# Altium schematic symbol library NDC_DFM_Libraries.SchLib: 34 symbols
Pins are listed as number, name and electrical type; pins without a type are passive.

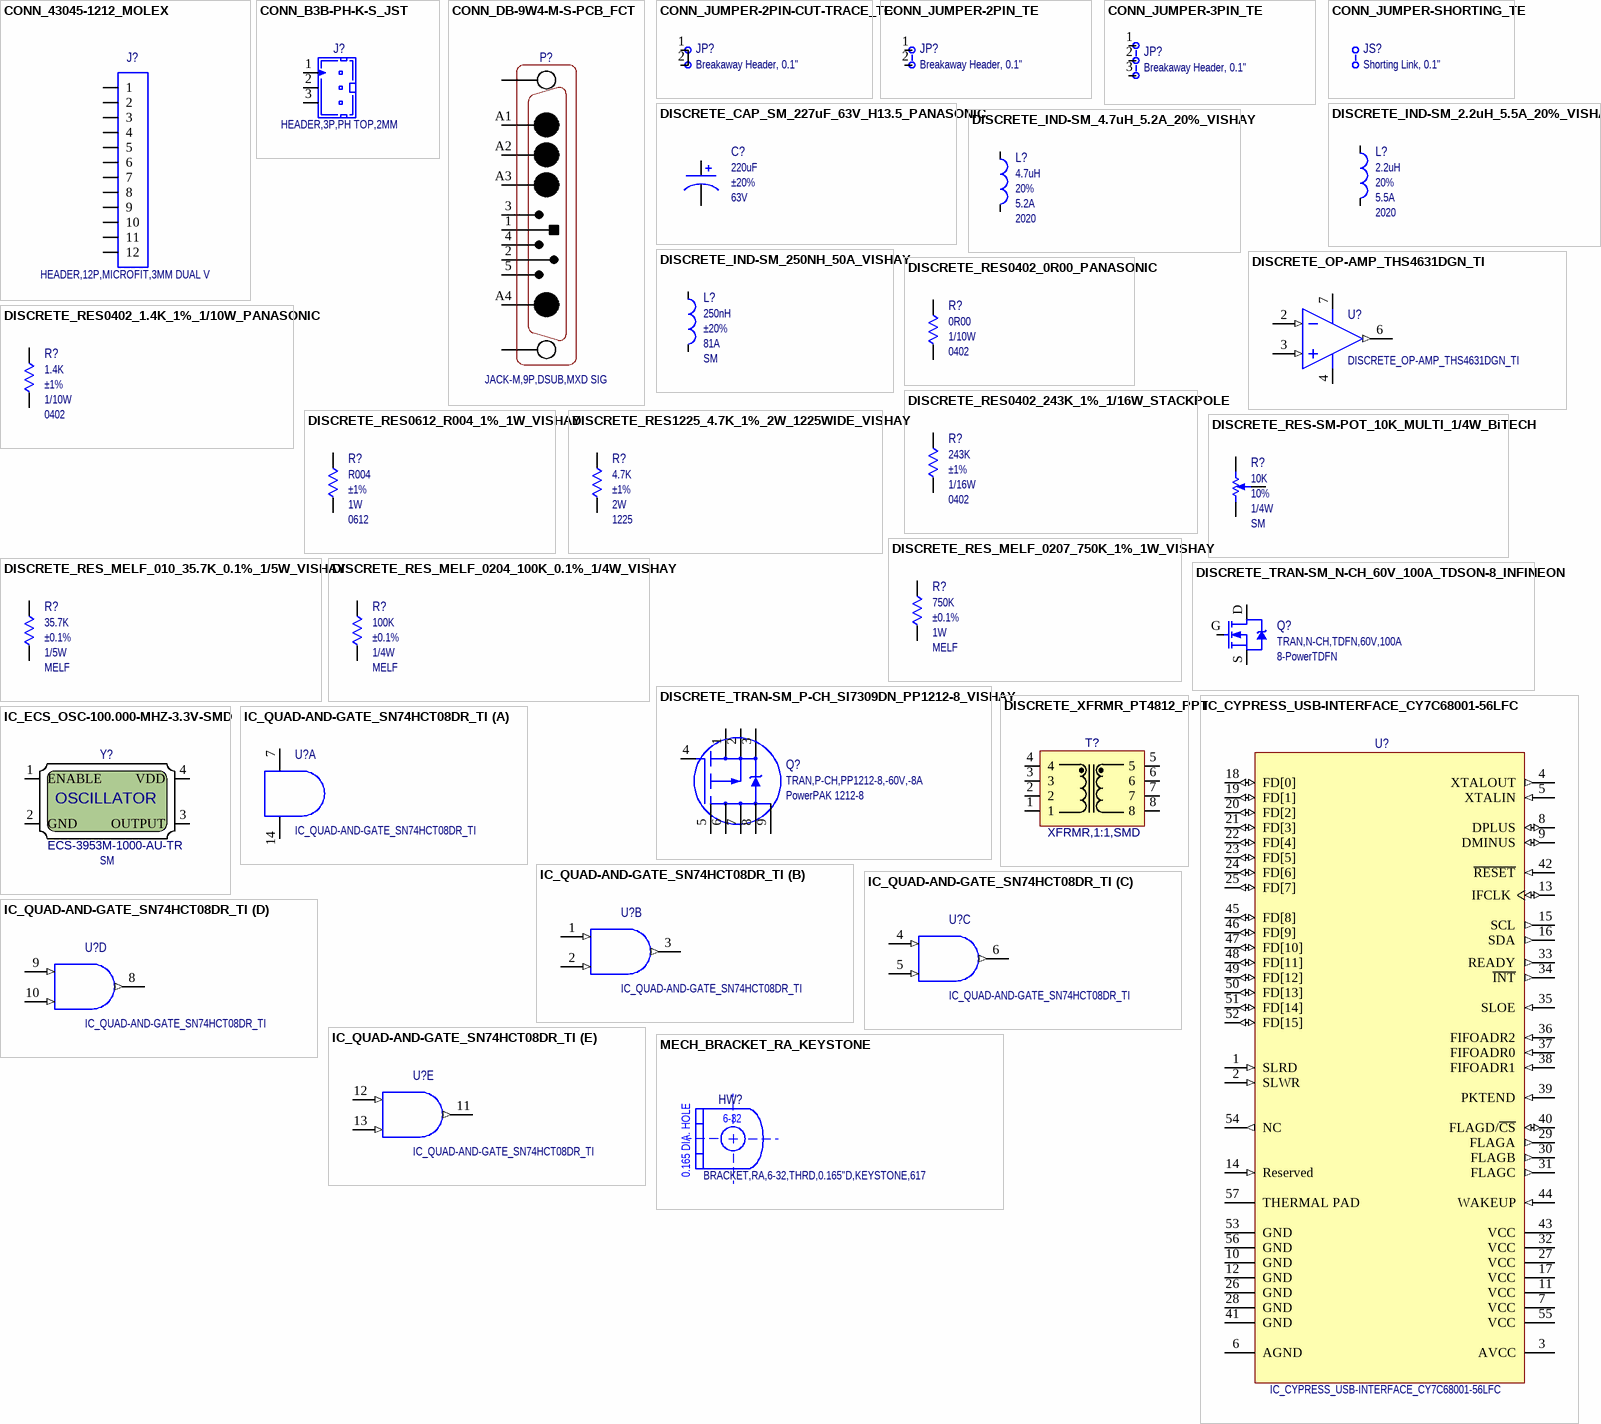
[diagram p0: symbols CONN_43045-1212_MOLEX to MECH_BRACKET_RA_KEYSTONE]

## CONN_43045-1212_MOLEX
designator J?, comment HEADER,12P,MICROFIT,3MM DUAL V
Manufacturer Part Number: 43045-1212; Manufacturer: MOLEX; CompanyPN: 1004237
footprint Molex_43045-1212 (Header, 12 Position, Pitch 3.0mm, Body 21.65 mm L X 7.37mm W, Height 9.91mm)
pins: 1, 2, 3, 4, 5, 6, 7, 8, 9, 10, 11, 12

## CONN_B3B-PH-K-S_JST
designator J?, comment HEADER,3P,PH TOP,2MM
Manufacturer: JST Sales America Inc; Manufacturer Part Number: B3B-PH-K-S(LF)(SN); CompanyPN: 1004223; Value: 2.00mm
footprint JST_B3B-PH-K-S
pins: 1 (power), 2 (power), 3 (power)

## CONN_DB-9W4-M-S-PCB_FCT
designator P?, comment JACK-M,9P,DSUB,MXD SIG
Manufacturer: FCT ELECTRONICS; Manufacturer Part Number: FM9W4P1-2519; CompanyPN: 1004225
footprint FCT_DB-9W4-M-S-PCB-MOD (FCT FM9W4P1-2464, Conn, DB, Mixed, 9 Pins, 4 Wide, Male, Straight, PCB Mt)
pins: 1, 2, 3, 4, 5, A1 (power), A2 (power), A3 (power), A4, C, C

## CONN_JUMPER-2PIN-CUT-TRACE_TE
designator JP?, comment Breakaway Header, 0.1"
Breakaway Header, 2.54mm (0.1") Pitch; Manufacturer: TE Connectivity / AMP; Manufacturer Part Number: 826646-2; CompanyPN: 1004233
footprint TE_HDR1X2-CUT-TRACE (Connector; Header; 2 Position)
pins: 1, 2

## CONN_JUMPER-2PIN_TE
designator JP?, comment Breakaway Header, 0.1"
Breakaway Header, 2.54mm (0.1") Pitch; Manufacturer: TE Connectivity / AMP; Manufacturer Part Number: 826646-2; CompanyPN: 1004232
footprint TE_HDR1X2 (Connector; Header; 2 Position)
pins: 1, 2

## CONN_JUMPER-3PIN_TE
designator JP?, comment Breakaway Header, 0.1"
Breakaway Header, 2.54mm (0.1") Pitch; Manufacturer: TE Connectivity / AMP; Manufacturer Part Number: 826646-2; CompanyPN: 1004234
footprint TE_HDR1X3 (Connector; Header; 3 Position)
pins: 1, 2, 3

## CONN_JUMPER-SHORTING_TE
designator JS?, comment Shorting Link, 0.1"  (mechanical)
Shorting Link, 2.54mm (0.1") Pitch; Manufacturer: Sullins Connector Solutions; Manufacturer Part Number: NPN02SXLN-RC; CompanyPN: 1004235
footprint SULLINS_JMPR-SOCKET-1X2

## DISCRETE_CAP_SM_227uF_63V_H13.5_PANASONIC
designator C?, comment value 220uF  Tolerance: ±20%  Voltage Rating: 63V  (hidden comment: CAP,ALUM,227,63V,20%,SMD)
Manufacturer: Panasonic Electronic Components; Manufacturer Part Number: EEV-FK1J221Q; CompanyPN: 1004222
footprint Panasonic_CAP_SM_H13
pins: 1, 2

## DISCRETE_IND-SM_2.2uH_5.5A_20%_VISHAY
designator L?, comment value 2.2uH  Package / Case: 2020  Tolerance: 20%  SatCur: 5.5A  (hidden comment: IND,2.2uH,2020,5.5A,20%)
Manufacturer: Vishay / Dale; Manufacturer Part Number: IHLP2020CZER2R2M11; CompanyPN: 1004229
footprint VISHAY_IND-IHLP2020CZ-11 (Low Profile, High Current IHLP® Inductor)
pins: 1, 2

## DISCRETE_IND-SM_4.7uH_5.2A_20%_VISHAY
designator L?, comment value 4.7uH  Package / Case: 2020  Tolerance: 20%  SatCur: 5.2A  (hidden comment: IND,4.7uH,202,5.2A,20%)
Manufacturer: Vishay / Dale; Manufacturer Part Number: IHLP2020CZER4R7M11; CompanyPN: 1004230
footprint VISHAY_IND-IHLP2020CZ-11 (Low Profile, High Current IHLP® Inductor)
pins: 1, 2

## DISCRETE_IND-SM_250NH_50A_VISHAY
designator L?, comment value 250nH  Tolerance: ±20%  PKG: SM  SatCur: 81A  (hidden comment: IND,250nH,SM,50A,81A ISAT)
Manufacturer: Wurth Electronics Inc; Manufacturer Part Number: 744309025; CompanyPN: 1004231
footprint VISHAY-IND-WE-HCM (WE-HCM SMD High-Current Flat Wire Inductor)
pins: 1, 2

## DISCRETE_OP-AMP_THS4631DGN_TI
designator U?
Operational Amplifier; Manufacturer: Texas Instruments; CompanyPN: 1004247
footprint TI_DGN8-EP (TSOP, 8-Leads, Body 3.1x3.1mm (max), Pitch 0.65mm, IPC Medium Density)
pins: 1 NC hidden, 2 IN- (in), 3 IN+ (in), 4 V- (power), 6 OUT (out), 7 V+ (power), 8 NC hidden

## DISCRETE_RES0402_0R00_PANASONIC
designator R?, comment value 0R00  Power: 1/10W  PKG: 0402  (hidden comment: RES,0R00,0402,1/10W)
Manufacturer Part Number: ERJ-2GE0R00X; Manufacturer: PANASONIC ELECTRONIC COMPONENTS; CompanyPN: 1004243; Voltage Rating: 50V
footprint STACKPOLE_RESC1005X04N(0402) (Chip Resistor, Body 1.0x0.5mm, Height 0.40mm, IPC Medium Density)
pins: 1, 2

## DISCRETE_RES0402_1.4K_1%_1/10W_PANASONIC
designator R?, comment value 1.4K  TOLERANCE: ±1%  Power: 1/10W  PKG: 0402  (hidden comment: RES,1.4K,0402,1%,1/10W)
Manufacturer Part Number: ERJ2RKF1401X; Manufacturer: PANASONIC ELECTRONIC COMPONENTS; CompanyPN: 1004244; Voltage Rating: 50V
footprint STACKPOLE_RESC1005X04N(0402) (Chip Resistor, Body 1.0x0.5mm, Height 0.40mm, IPC Medium Density)
pins: 1, 2

## DISCRETE_RES0402_243K_1%_1/16W_STACKPOLE
designator R?, comment value 243K  Tolerance: ±1%  Power: 1/16W  PKG: 0402  (hidden comment: RES,243K,0402,1%,1/16W)
Manufacturer: Stackpole Electronics Inc; Manufacturer Part Number: RMCF0402FT243K; CompanyPN: 1004240; Voltage Rating: 50V
footprint STACKPOLE_RESC1005X04N(0402) (Chip Resistor, Body 1.0x0.5mm, Height 0.40mm, IPC Medium Density)
pins: 1, 2

## DISCRETE_RES0612_R004_1%_1W_VISHAY
designator R?, comment value R004  Tolerance: ±1%  Power: 1W  PKG: 0612  (hidden comment: RES-SENSOR,R004,0612,1%,1W)
RES,R004,0612,1%,1W; Manufacturer: Vishay / Dale; Manufacturer Part Number: WSK06124L000FEA; CompanyPN: 1004241
footprint VISHAY_RES1632(0612)-RSNS (4-Terminal, 1W, Current-sense Resistor)
pins: 1, 2

## DISCRETE_RES1225_4.7K_1%_2W_1225WIDE_VISHAY
designator R?, comment value 4.7K  Tolerance: ±1%  Power: 2W  PKG: 1225  (hidden comment: RES,4.7K,1225WIDE,1%,2W)
Manufacturer: Vishay / Draloric; Manufacturer Part Number: RCL12254K70FKEG; Voltage Rating: 200V; CompanyPN: 1004242
footprint VISHAY_RES3263(1225) (Long Side Termination Thick Film Chip Resistor, 2W)
pins: 1, 2

## DISCRETE_RES-SM-POT_10K_MULTI_1/4W_BiTECH
designator R?, comment value 10K  Tolerance: 10%  Power: 1/4W  PKG: SM  (hidden comment: RES-POT,10K,SM,10%,1/4W)
Manufacturer: BI Technologies / TT electronics; Manufacturer Part Number: 44WR10KLFT7; CompanyPN: 1004245; Voltage Rating: 300V
footprint RPOT_3224W_44W (Potentiometer, SMT 4mm, Multiturn Cermet, Sealed)
pins: 1 CCW, 2 W, 3 CW
1 alternate drawing of the same symbol

## DISCRETE_RES_MELF_010_35.7K_0.1%_1/5W_VISHAY
designator R?, comment value 35.7K  Tolerance: ±0.1%  Power: 1/5W  PKG: MELF  (hidden comment: RES,35.7K,MELF010,0.1%,1/5W)
Manufacturer: Vishay / Draloric; Manufacturer Part Number: SMM01020D3572BB300; CompanyPN: 1004252; Voltage Rating: 200V
footprint VISHAY_MELF-MMU-0102
pins: 1, 2

## DISCRETE_RES_MELF_0204_100K_0.1%_1/4W_VISHAY
designator R?, comment value 100K  Power: 1/4W  Tolerance: ±0.1%  PKG: MELF  (hidden comment: RES,100K,MELF0204,0.1%,1/4W)
Manufacturer: Vishay / Draloric; Manufacturer Part Number: SMM02040E1003BB300; CompanyPN: 1004251; Voltage Rating: 200V
footprint VISHAY_MELF-MMA-0204
pins: 1, 2

## DISCRETE_RES_MELF_0207_750K_1%_1W_VISHAY
designator R?, comment value 750K  Power: 1W  Tolerance: ±0.1%  PKG: MELF  (hidden comment: RES,750K,MELF0204,1%,1W)
Manufacturer: Vishay / Beyschlag; Manufacturer Part Number: MMB02070C7503FB200; CompanyPN: 1004253; Voltage Rating: 350V
footprint VISHAY_MELF-MMB-0207
pins: 1, 2

## DISCRETE_TRAN-SM_N-CH_60V_100A_TDSON-8_INFINEON
designator Q?, comment TRAN,N-CH,TDFN,60V,100A  Package / Case: 8-PowerTDFN
Manufacturer: Infineon Technologies; Manufacturer Part Number: BSC028N06NS; CompanyPN: 1004249
footprint INFINEON_TDSON-8 (INFINEON  SuperS08 125W)
pins: D, G, S

## DISCRETE_TRAN-SM_P-CH_SI7309DN_PP1212-8_VISHAY
designator Q?, comment TRAN,P-CH,PP1212-8,-60V,-8A  PKG: PowerPAK 1212-8
Manufacturer: Vishay; Manufacturer Part Number: SI7309DN; CompanyPN: 1004248
footprint VISHAY_QFN65P330X330X112-10N (QFN, 10-Leads, Body 3.4x3.4mm (max), Pitch 0.65mm, IPC Medium Density)
pins: 1 S "Source", 2 S "Source", 3 S "Source", 4 G "Gate", 5 D "Drain", 6 D "Drain", 7 D "Drain", 8 D "Drain", 9 D "Drain"

## DISCRETE_XFRMR_PT4812_PPT
designator T?, comment XFRMR,1:1,SMD
Manufacturer: PPT Magnetics (China); Manufacturer Part Number: PT-4812; CompanyPN: 1004239
footprint PPT_PT4812 (Transformer for Digital Audio Data Transmission)
pins: 1, 2, 3, 4, 5, 6, 7, 8

## IC_CYPRESS_USB-INTERFACE_CY7C68001-56LFC
designator U?
CY7C68001-56LFC, EZ-USB SX2 High-Speed USB Interface; Manufacturer: Cypress Semiconductor; CompanyPN: 1004224
footprint CYPRESS_QFN50P800X800-HS-57 (Quad Flat No Lead; 56 Terminals; Body 8 x 8 mm; Pitch 0.5 mm, Punch Version)
pins: 1 SLRD (in), 2 SLWR (in), 3 AVCC (power), 4 XTALOUT (out), 5 XTALIN (in), 6 AGND (power), 7 VCC (power), 8 DPLUS (io), 9 DMINUS (io), 10 GND (power), 11 VCC (power), 12 GND (power), 13 IFCLK (io), 14 Reserved (in), 15 SCL (out), 16 SDA (out), 17 VCC (power), 18 FD[0] (io), 19 FD[1] (io), 20 FD[2] (io), 21 FD[3] (io), 22 FD[4] (io), 23 FD[5] (io), 24 FD[6] (io), 25 FD[7] (io), 26 GND (power), 27 VCC (power), 28 GND (power), 29 FLAGA (out), 30 FLAGB (out), 31 FLAGC (out), 32 VCC (power), 33 READY (out), 34 ~{INT} (out), 35 SLOE (in), 36 FIFOADR2 (in), 37 FIFOADR0 (in), 38 FIFOADR1 (in), 39 PKTEND (in), 40 FLAGD/~{CS} (io), 41 GND (power), 42 ~{RESET} (in), 43 VCC (power), 44 WAKEUP (in), 45 FD[8] (io), 46 FD[9] (io), 47 FD[10] (io), 48 FD[11] (io), 49 FD[12] (io), 50 FD[13] (io), 51 FD[14] (io), 52 FD[15] (io), 53 GND (power), 54 NC (out), 55 VCC (power), 56 GND (power), 57 THERMAL PAD (power)

## IC_ECS_OSC-100.000-MHZ-3.3V-SMD
designator Y?, comment ECS-3953M-1000-AU-TR  PKG: SM
OSC 100.000 MHZ 3.3V SMD; Manufacturer: ECS Inc; CompanyPN: 1004238
footprint ECS_3953M-1000-AU-TR (SMD CLOCK OSCILLATOR)
pins: 1 ENABLE, 2 GND, 3 OUTPUT, 4 VDD

## IC_QUAD-AND-GATE_SN74HCT08DR_TI
designator U?
LogicGate_AND; Manufacturer: Texas Instruments; Manufacturer Part Number: SN74AHCT08DR; CompanyPN: 1004254
footprint TI_SOIC_14 (SOIC, 14-Leads, Body 8.65x3.95mm, Pitch 1.27mm, IPC Medium Density)
part A pins: 7 GND (power), 14 VCC (power)
part B pins: 1 A (in), 2 B (in), 3 Y (out)
part C pins: 4 A (in), 5 B (in), 6 Y (out)
part D pins: 8 Y (out), 9 A (in), 10 B (in)
part E pins: 11 Y (out), 12 A (in), 13 B (in)

## MECH_BRACKET_RA_KEYSTONE
designator HW?, comment BRACKET,RA,6-32,THRD,0.165"D,KEYSTONE,617  (mechanical)
Manufacturer: Keystone Electronics; Manufacturer Part Number: 617; CompanyPN: 1004221
footprint KEYSTONE_BRACKET-617 (BRACKET,RIGHT-ANGL,THRD,6-32 (STEEL))

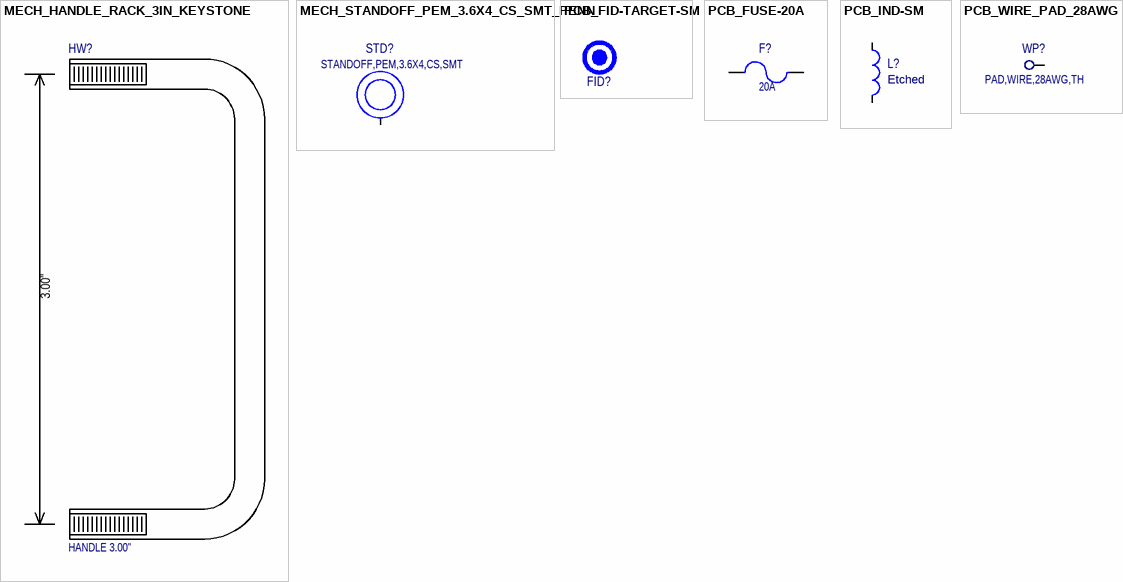
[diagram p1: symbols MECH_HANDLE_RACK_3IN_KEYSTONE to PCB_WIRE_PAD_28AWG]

## MECH_HANDLE_RACK_3IN_KEYSTONE
designator HW?, comment HANDLE 3.00"  (mechanical)
HANDLE,ALUM,BLK,3.00",8-32; Manufacturer: Keystone Electronics; Manufacturer Part Number: 7173; CompanyPN: 1004228
footprint KEYSTONE_HANDLE-7173 (HANDLE,ALUM,BLK,3.00",8-32)

## MECH_STANDOFF_PEM_3.6X4_CS_SMT_PENN
designator STD?, comment STANDOFF,PEM,3.6X4,CS,SMT
Manufacturer Part Number: SMTSO-3.6-4DT; Manufacturer: Penn Engineering; CompanyPN: 1004246; Value: SMTSO-3.6-4DT
footprint PENN_PEM-SMTSO-3.6-4DT (PEM Standoff SMTSO-3.6-4DT, Matte Tin, Surface Mount Solder, ReelFast)
pins: 1 MH

## PCB_FID-TARGET-SM
designator FID?, comment FID  (value not drawn)  (no BOM)
PCB FEATURE; CompanyPN: 1004226
footprint PCB_FID-TARGET-SM

## PCB_FUSE-20A
designator F?, comment 20A  (net tie, no BOM)
PCB FEATURE; CompanyPN: 1004227
footprint PCB_FUSE-20A
pins: 1, 2

## PCB_IND-SM
designator L?, comment Package / Case: Etched  (hidden comment: IND,Etched)  (net tie, no BOM)
CompanyPN: 1004255; PKG: SM
footprint GENERIC_PLANAR-1:1
pins: 1, 2

## PCB_WIRE_PAD_28AWG
designator WP?, comment PAD,WIRE,28AWG,TH
Manufacturer: PCB FEATURE; CompanyPN: 1004250
footprint GENERIC_WP28 (PAD,WIRE,28AWG,TH)
pins: 1 WP28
